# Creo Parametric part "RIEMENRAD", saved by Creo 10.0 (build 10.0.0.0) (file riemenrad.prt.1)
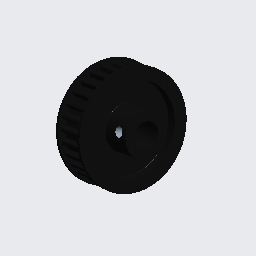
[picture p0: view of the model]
Units: millimeter Newton Second (mmNs); MM, TONNE, SECS

Created from: PRT0004.PRT

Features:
  1. coordinate system "16252800"
  2. imported feature "Import-ke ID 5"
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
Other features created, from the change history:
  datum plane "DTM1"
  extruded cut "Profil 1"

Other named items: DEFAULT_1, NOTE_0

Layers: INTFCLR_4658

Notes: 16252800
